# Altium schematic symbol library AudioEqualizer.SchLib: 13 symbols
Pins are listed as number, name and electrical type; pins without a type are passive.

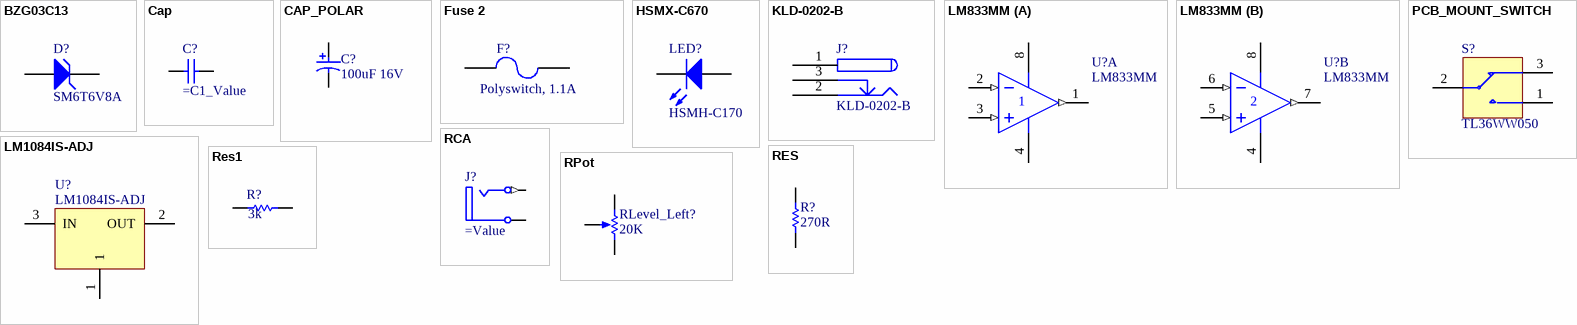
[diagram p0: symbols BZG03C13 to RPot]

## BZG03C13
designator D?, comment SM6T6V8A
Zener Diode, 6.2V, 5W; Manufacturer: Microsemi
footprint DO214
pins: 1 A, 2 K

## Cap
designator C?
Capacitor
simulation model CAP (Capacitor)
signal-integrity model Cap
footprint C1206
pins: 1, 2

## CAP_POLAR
designator C?, comment 100uF 16V
Polar Capacitor
footprint MCCT-B
pins: 1, 2

## Fuse 2
designator F?, comment Polyswitch, 1.1A
Polyswitch 1.1A, Raychem RUE110
footprint PIN-W2/E2.8
simulation model FUSE (Spice Subcircuit)
pins: 1, 2

## HSMX-C670
designator LED?, comment HSMH-C170
Typical RED GaAs SMD LED Agilent make; AEMS Code: 2610081
footprint SMD _LED
simulation model LED1 (Diode)
pins: 1 A, 2 K

## KLD-0202-B
designator J?
Low Voltage Power Supply Connector; Manufacturer: Kycon; AEMS Code: 3510211
footprint KLD-0202
pins: 1 (power), 1A (power), 1B (power), 2 (power), 2A (power), 2B (power), 3 (power), 3A (power), 3B (power)

## LM833MM
designator U?
Dual Audio Operational Amplifier; PackageDocument: 2000
footprint MUA08A
3D model MUA08A (Shrink Small Outline; 8 Leads; Body Width 3 mm; Pitch 0.65 mm)
simulation model LM833 (SUBCKT)
pins on every part: 4 V- (power), 8 V+ (power)
part A pins: 1 OUT (out), 2 IN- (in), 3 IN+ (in)
part B pins: 5 IN+ (in), 6 IN- (in), 7 OUT (out)

## LM1084IS-ADJ
designator U?
5A Low Dropout Possitive Regulators
footprint TO-263
pins: 1 "Output", 2 OUT (power) "Output", 3 IN (power) "Input"

## PCB_MOUNT_SWITCH
designator S?, comment TL36WW050
SPDT Subminiature Toggle Switch
footprint B3FS_SWITCH
pins: 1, 2, 3

## RCA
designator J?
RCA Phono Jack, Right Angle, Thru-Hole, Snap-In; PCB_Layout: Complies with manufacturer's recommendation.; DrillAndSlotSize: Corresponds to nominal value.
footprint RCA/4.5-H2
signal-integrity model RCA
pins: 1A Ground (power) "Outer Shield (Sleeve)", 2B Signal (out) "Center Pin (Plug Tip)"

## RES
designator R?, comment 270R
Resistor; AEMS Code: 1200430
footprint 3216[1206]
pins: 1, 2

## Res1
designator R?, comment 3k
Resistor
simulation model RESISTOR (Resistor)
signal-integrity model Res
footprint 3216[1206]
pins: 1, 2

## RPot
designator RLevel_Left?  value 20K  (hidden comment: RPot)
Potentiometer; Sim Note: Enter the Resistance value and the set point into parameter fields.; Set Position: 0.5
footprint VR5
simulation model POT (Potentiometer)
pins: 1 TOP, 2 BOT, 3 TAP
1 alternate drawing of the same symbol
